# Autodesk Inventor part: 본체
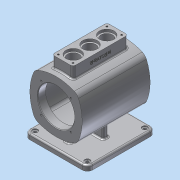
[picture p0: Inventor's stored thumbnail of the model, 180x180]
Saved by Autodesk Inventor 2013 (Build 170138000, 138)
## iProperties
Created: 2015-11
Part Number: 본체
Material: 알루미늄 6061
Document SubType Name: Modeling
Designer: mduedu
Density: 2.71 g/cm^3
Mass: 1533.89 g
Surface Area: 1429.23 cm^2
Volume: 566.012 cm^3
Author: mduedu
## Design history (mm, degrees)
sketch "스케치2"
  geometry: L1 (0, 250)-(0, -250); L2 (250, 0)-(-250, 0); L3 (-50, 50)-(50, 50); L4 (50, 50)-(50, -50); L5 (50, -50)-(-50, -50); L6 (-50, -50)-(-50, 50); A1 r 90 centre (-40, 0) between (40.415, -40.415) and (40.415, 40.415); A2 r 90 centre (40, 0) between (-40.415, 40.415) and (-40.415, -40.415); A3 r 90 centre (0, -40) between (40.415, 40.415) and (-40.415, 40.415); A4 r 90 centre (0, 40) between (-40.415, -40.415) and (40.415, -40.415); 2 further points
  constraints: 12 end point, 8 point on circle, 4 centre point, 4 tangent, 3 perpendicular, 2 horizontal alignment, 2 midpoint, 2 parallel, 2 symmetric about line, 1 coincident, 1 equal radius, 1 horizontal, 1 vertical, 1 vertical alignment, 2 other
  dimensions: "d6" = 500 distance of L1.start L1.end; "d8" = 500 distance of L2.start L2.end; "d9" = 100 distance of L3.end L4.end; "d11" = 90 radius of A3
extrude "돌출1" new body sketch "스케치2" stored distance "d12" = 130; taper "d13" = 0 deg
fillet "모깎기6" dims "d30" = 15
feature "쉘1" dims "d31" = 15, "d32" = 6, "d33" = 15
sketch "스케치5"
  geometry: C1 r 35 at (0, 0); 1 further point
  constraints: 1 centre point, 1 coincident
  dimensions: "d34" = 70 diameter of C1
extrude "돌출3" cut sketch "스케치5" stored distance "d36" = 3; taper "d37" = 0 deg
node "작업 평면1"
sketch "스케치6"
  geometry: L1 (-65, -60)-(65, -60); L2 (65, -60)-(65, 60); L3 (65, 60)-(-65, 60); L4 (-65, 60)-(-65, -60); L5 (-65, -60)-(65, 60); L6 (65, -60)-(-65, 60); 1 further point
  constraints: 12 end point, 2 midpoint, 2 parallel, 1 horizontal, 1 perpendicular
  dimensions: "d41" = 120 distance of L3.end L1.start; "d43" = 130 distance of L2.end L3.end
extrude "돌출4" join sketch "스케치6" distance "d44" = 10; taper "d45" = 0 deg
sketch "스케치8"
  geometry: L1 (-60, -70)-(60, -70) reference; L2 (0, -50)-(0, -70); L3 (-30, -44.853)-(-30, -70); L4 (30, -44.853)-(30, -70); L5 (-30, -70)-(30, -70); A1 r 90 centre (0, 40) between (-34.941, -42.941) and (34.941, -42.941) reference; A2 r 90 centre (0, 40) between (-30, -44.853) and (30, -44.853); 1 further point
  constraints: 8 end point, 5 point on circle, 2 perpendicular, 2 symmetric about line, 1 centre point, 1 midpoint, 1 point on line
  dimensions: "d48" = 60 distance between parallel lines of L4 L3
extrude "돌출5" join sketch "스케치8" stored distance "d50" = 10; taper "d51" = 0 deg
sketch "스케치17"
  geometry: L1 (65, -50)-(-65, -50) reference; L2 (-65, -70)-(65, -70) reference; L3 (37.721, -50)-(45, -70); L4 (65, -80)-(65, -70) reference; 1 further point
  constraints: 2 end point, 2 point on line
  dimensions: "d128" = 20 distance from line of L3.end L4; "d129" = 110 deg angle of L3 L2
feature "리브1" sketch "스케치17" dims "d130" = 1, "d131" = 10, "d132" = 0, "d133" = 0, "d134" = 1, "d135" = 1
fillet "모깎기17" dims "d136" = 3
fillet "모깎기18" dims "d137" = 3
fillet "모깎기14" dims "d78" = 3
sketch "스케치12"
  geometry: L1 (0, 0)-(28.284, 28.284); L2 (0, 0)-(40, 0); A1 r 40 centre (0, 0) between (28.284, 28.284) and (40, 0); 2 further points
  constraints: 4 end point, 2 coincident, 2 point on circle, 1 centre point, 1 horizontal
  dimensions: "d79" = 80 diameter of A1; "d80" = 45 deg angle of L2 L1
hole "구멍2" sketch "스케치12" at (28.284, 28.284) diameter "d82" = 3.242; stored, may be unused: countersink angle "d86" = 90 deg, drill point angle "d88" = 118 deg; dims "d83" = 9, "d84" = 10, "d85" = 2, "d87" = 11
node "작업 평면2"
sketch "스케치13"
  geometry: L1 (-52.5, -20)-(52.5, -20); L2 (52.5, -20)-(52.5, 20); L3 (52.5, 20)-(-52.5, 20); L4 (-52.5, 20)-(-52.5, -20); L5 (-52.5, -20)-(52.5, 20); L6 (52.5, -20)-(-52.5, 20); 1 further point
  constraints: 12 end point, 2 midpoint, 2 parallel, 1 horizontal, 1 perpendicular
  dimensions: "d93" = 105 distance of L2.end L3.end; "d95" = 40 distance of L1.end L2.end
extrude "돌출8" join sketch "스케치13" stored distance "d96" = 80; taper "d97" = 0 deg
fillet "모깎기15" dims "d98" = 5
fillet "모깎기16" dims "d99" = 3
sketch "스케치14"
  geometry: L1 (-52.5, 15)-(-52.5, -15) reference; L2 (52.5, -15)-(52.5, 15) reference; L3 (-52.5, 0)-(52.5, 0); 4 further points
  constraints: 2 end point, 2 midpoint, 2 point on line, 1 coincident
  dimensions: "d100" = 32 distance of point (-32, 0) point (0, 0); "d102" = 32 distance of point (32, 0) point (0, 0) (derived)
hole "구멍3" sketch "스케치14" at (-32, 0), (0, 0), (32, 0) diameter "d103" = 22; stored, may be unused: countersink angle "d107" = 90 deg, drill point angle "d109" = 118 deg; dims "d104" = 8, "d105" = 28, "d106" = 5, "d108" = 10
sketch "스케치15"
  geometry: L1 (46.5, -14)-(-46.5, -14); L2 (-46.5, -14)-(-46.5, 14); L3 (-46.5, 14)-(46.5, 14); L4 (46.5, 14)-(46.5, -14); L5 (46.5, -14)-(-46.5, 14); L6 (-46.5, -14)-(46.5, 14); L7 (47.5, 20)-(-47.5, 20) reference; L8 (-52.5, 15)-(-52.5, -15) reference; 5 further points
  constraints: 12 end point, 4 coincident, 2 midpoint, 2 parallel, 1 horizontal, 1 perpendicular
  dimensions: "d110" = 6 distance between parallel lines of L3 L7; "d111" = 6 distance between parallel lines of L2 L8
hole "구멍4" sketch "스케치15" at (-46.5, 14), (46.5, 14), (46.5, -14), (-46.5, -14) diameter "d112" = 3.242; stored, may be unused: countersink angle "d116" = 90 deg, drill point angle "d118" = 118 deg; dims "d113" = 10, "d114" = 28, "d115" = 5, "d117" = 13
sketch "스케치16"
  geometry: L1 (33.5, 0)-(61.5, 0) reference; L2 (47.5, 0)-(47.5, -150); L3 (112.5, -150)-(-17.5, -150) reference; 1 further point
  constraints: 2 end point, 2 midpoint, 1 point on line, 1 other
  dimensions: "d122" = 11 distance from line of point (47.5, -11) L1
feature "엠보싱2" sketch "스케치16" dims "d34" = 70, "d123" = 0.5, "d124" = 0
chamfer "모따기1" distance "d125" = 1; stored, may be unused: second distance "d126" = 2, angle "d127" = 45 deg
fillet "모깎기19" dims "d138" = 10
sketch "스케치18"
  geometry: L1 (65, -50)-(65, 50) reference; L2 (-55, -60)-(55, -60) reference; L3 (-65, 50)-(-65, -50) reference; L4 (55, 60)-(-55, 60) reference; A1 r 10 centre (55, 50) between (65, 50) and (55, 60) reference; A2 r 10 centre (55, -50) between (55, -60) and (65, -50) reference; A3 r 10 centre (-55, -50) between (-65, -50) and (-55, -60) reference; A4 r 10 centre (-55, 50) between (-55, 60) and (-65, 50) reference; 5 further points
  constraints: 4 coincident
hole "구멍5" sketch "스케치18" at (-55, 50), (55, 50), (55, -50), (-55, -50) diameter "d139" = 6; stored, may be unused: countersink angle "d143" = 90 deg, drill point angle "d145" = 118 deg; dims "d140" = 6, "d141" = 10, "d142" = 2, "d144" = 8
fillet "모깎기20" dims "d146" = 3
node "솔리드1"
mirror "대칭4"
pattern_circular "원형 패턴1" dims angle "d90" = 360 deg
mirror "대칭3"
node "투영된 루프1"
